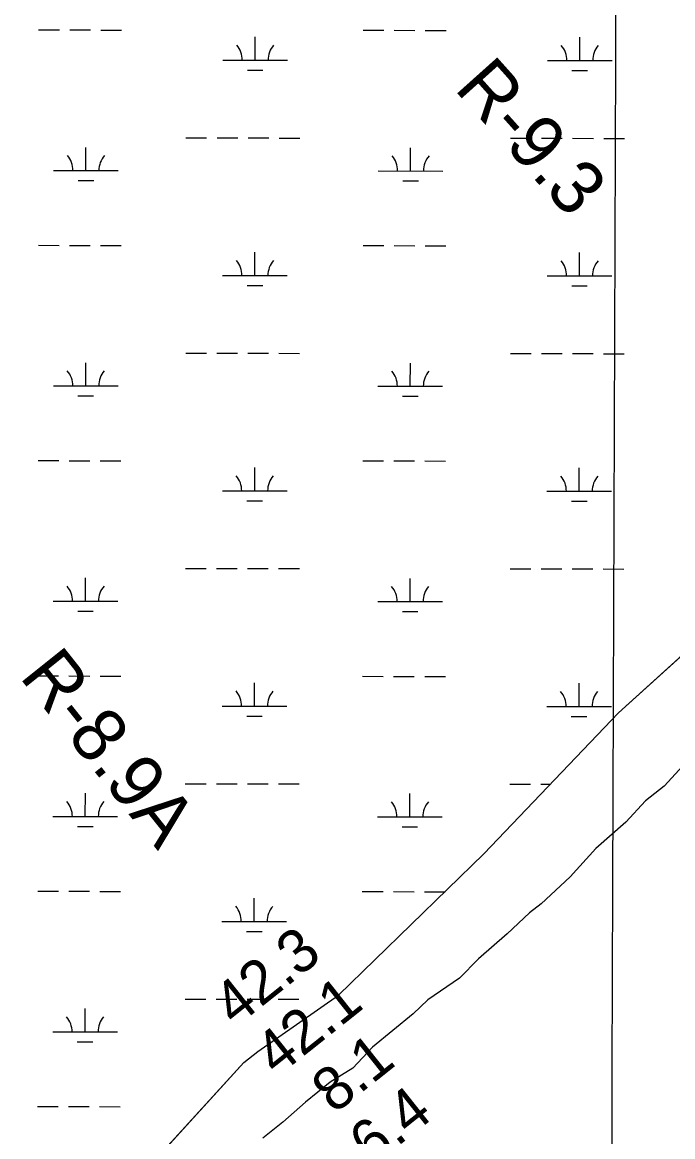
# Model space of a CAD drawing. Extents: x 3148686 to 3186545, y 916144 to 941516.
# Drawn here: x 3154623 to 3155629, y 922106 to 923828 of the extents above; entities that cross this region are included whole.
import ezdxf

# ---------------------------------------------------------------- set-up
doc = ezdxf.new("R2010")
doc.units = 0
for name, color, linetype in [('V-GRID-MAJR', 7, 'Continuous'), ('V-RIVR-EDGE', 7, 'Continuous'), ('V-RIVR-RANG', 7, 'Continuous'), ('V-RIVR-RANG-IDEN', 7, 'Continuous'), ('V-SITE-VEGE', 7, 'Continuous'), ('V-WETL-SWMP', 7, 'Continuous')]:
    doc.layers.add(name, color=color, linetype=linetype)

msp = doc.modelspace()

# ---------------------------------------------------------------- linework, layer by layer
at = {"layer": 'V-GRID-MAJR'}
msp.add_spline([(3155532.8, 921545.6), (3155553.9, 927607.5), (3155575.1, 933670.5), (3155596.3, 939733.5), (3155596.3, 939734.6)], degree=3, dxfattribs=at)
at = {"layer": 'V-RIVR-EDGE'}
msp.add_lwpolyline([(3155667.2, 922703.8), (3155615.3, 922647.6), (3155586.9, 922624.6), (3155556.3, 922591.7), (3155509.8, 922551.4), (3155470.3, 922507.5), (3155425.2, 922465.8), (3155407.1, 922451.6), (3155372.9, 922419.4), (3155328.5, 922380.9), (3155299, 922350.8), (3155250.3, 922317.3), (3155227.6, 922296), (3155164.4, 922244.1), (3155134.1, 922211.9), (3155099, 922190.3), (3155061, 922159.2), (3155026.1, 922128.5), (3154995.2, 922103.7)], dxfattribs=at)
at = {"layer": 'V-SITE-VEGE'}
for p, q in [((3155545.1, 922760.8), (3155916.4, 923097.1)), ((3155336.9, 922542.9), (3155545.1, 922760.8)), ((3155112, 922324.4), (3155336.9, 922542.9)), ((3154987, 922237.4), (3155112, 922324.4)), ((3154965.6, 922220.8), (3154987, 922237.4)), ((3154789.5, 922027.6), (3154965.6, 922220.8))]:
    msp.add_line(p, q, dxfattribs=at)
at = {"layer": 'V-WETL-SWMP'}
for p, q in [((3154648.3, 923815.8), (3154680.3, 923815.8)), ((3154696.3, 923815.8), (3154728.3, 923815.8)), ((3154744.3, 923815.7), (3154776.3, 923815.7)), ((3154983.1, 923769.1), (3154983.1, 923805.1)), ((3155150.2, 923815.3), (3155182.2, 923815.3)), ((3155198.2, 923815.3), (3155230.2, 923815.2)), ((3155246.2, 923815.2), (3155278.2, 923815.2)), ((3155485, 923768.5), (3155485, 923804.5)), ((3154933.1, 923769.1), (3155033.1, 923769)), ((3155435, 923768.6), (3155535, 923768.5)), ((3154971.1, 923753.6), (3154995.1, 923753.6)), ((3155473, 923753.1), (3155497, 923753.1)), ((3154876.1, 923649.1), (3154908.1, 923649.1)), ((3154924.1, 923649), (3154956.1, 923649)), ((3154972.1, 923649), (3155004.1, 923649)), ((3155020.1, 923648.9), (3155052.1, 923648.9)), ((3155378, 923648.6), (3155410, 923648.5)), ((3155426, 923648.5), (3155458, 923648.5)), ((3155474, 923648.5), (3155506, 923648.4)), ((3155522, 923648.4), (3155554, 923648.4)), ((3154721.5, 923598.5), (3154721.5, 923634.5)), ((3155223.4, 923598), (3155223.4, 923634)), ((3154671.5, 923598.6), (3154771.5, 923598.5)), ((3155173.4, 923598), (3155273.4, 923597.9)), ((3154709.5, 923583.1), (3154733.5, 923583.1)), ((3155211.4, 923582.6), (3155235.4, 923582.5)), ((3154647.9, 923483.2), (3154679.9, 923483.1)), ((3154695.9, 923483.1), (3154727.9, 923483.1)), ((3154743.9, 923483.1), (3154775.9, 923483)), ((3155149.9, 923482.6), (3155181.9, 923482.6)), ((3155197.9, 923482.6), (3155229.9, 923482.5)), ((3155245.9, 923482.5), (3155277.9, 923482.5)), ((3154982.7, 923436.4), (3154982.8, 923472.4)), ((3155484.7, 923435.8), (3155484.7, 923471.8)), ((3154932.7, 923436.4), (3155032.7, 923436.3)), ((3155434.7, 923435.9), (3155534.7, 923435.8)), ((3154970.7, 923421), (3154994.7, 923420.9)), ((3155472.6, 923420.4), (3155496.6, 923420.4)), ((3154721.1, 923265.8), (3154721.2, 923301.8)), ((3154875.8, 923316.4), (3154907.8, 923316.4)), ((3154923.8, 923316.4), (3154955.8, 923316.3)), ((3154971.8, 923316.3), (3155003.8, 923316.3)), ((3155019.8, 923316.3), (3155051.8, 923316.2)), ((3155223, 923265.3), (3155223.1, 923301.3)), ((3155377.7, 923315.9), (3155409.7, 923315.9)), ((3155425.7, 923315.8), (3155457.7, 923315.8)), ((3155473.7, 923315.8), (3155505.7, 923315.8)), ((3155521.7, 923315.7), (3155553.7, 923315.7)), ((3154671.1, 923265.9), (3154771.1, 923265.8)), ((3154709.1, 923250.4), (3154733.1, 923250.4)), ((3155173, 923265.4), (3155273, 923265.3)), ((3155211, 923249.9), (3155235, 923249.9)), ((3154647.6, 923150.5), (3154679.6, 923150.5)), ((3154695.6, 923150.4), (3154727.6, 923150.4)), ((3154743.6, 923150.4), (3154775.6, 923150.4)), ((3155149.5, 923150), (3155181.5, 923149.9)), ((3155197.5, 923149.9), (3155229.5, 923149.9)), ((3155245.5, 923149.9), (3155277.5, 923149.8)), ((3154982.4, 923103.7), (3154982.4, 923139.7)), ((3155484.3, 923103.2), (3155484.3, 923139.2)), ((3154932.4, 923103.8), (3155032.4, 923103.7)), ((3155434.3, 923103.2), (3155534.3, 923103.1)), ((3154970.4, 923088.3), (3154994.4, 923088.3)), ((3155472.3, 923087.8), (3155496.3, 923087.7)), ((3154875.4, 922983.7), (3154907.4, 922983.7)), ((3154923.4, 922983.7), (3154955.4, 922983.7)), ((3154971.4, 922983.6), (3155003.4, 922983.6)), ((3155019.4, 922983.6), (3155051.4, 922983.6)), ((3155377.3, 922983.2), (3155409.3, 922983.2)), ((3155425.3, 922983.2), (3155457.3, 922983.1)), ((3155473.3, 922983.1), (3155505.3, 922983.1)), ((3155521.3, 922983.1), (3155553.3, 922983)), ((3154720.8, 922933.2), (3154720.8, 922969.2)), ((3155222.7, 922932.6), (3155222.7, 922968.6)), ((3154670.8, 922933.2), (3154770.8, 922933.1)), ((3155172.7, 922932.7), (3155272.7, 922932.6)), ((3154708.8, 922917.7), (3154732.8, 922917.7)), ((3155210.7, 922917.2), (3155234.7, 922917.2)), ((3154647.2, 922817.8), (3154679.2, 922817.8)), ((3154695.2, 922817.8), (3154727.2, 922817.7)), ((3154743.2, 922817.7), (3154775.2, 922817.7)), ((3154982, 922771), (3154982.1, 922807)), ((3155149.2, 922817.3), (3155181.2, 922817.2)), ((3155197.2, 922817.2), (3155229.2, 922817.2)), ((3155245.2, 922817.2), (3155277.2, 922817.1)), ((3155483.9, 922770.5), (3155484, 922806.5)), ((3154932, 922771.1), (3155032, 922771)), ((3155433.9, 922770.6), (3155533.9, 922770.4)), ((3154970, 922755.6), (3154994, 922755.6)), ((3155471.9, 922755.1), (3155495.9, 922755.1)), ((3154875.1, 922651.1), (3154907.1, 922651)), ((3154923.1, 922651), (3154955.1, 922651)), ((3154971.1, 922651), (3155003.1, 922650.9)), ((3155019.1, 922650.9), (3155051.1, 922650.9)), ((3155377, 922650.5), (3155409, 922650.5)), ((3155425, 922650.5), (3155439.7, 922650.5)), ((3154720.4, 922600.5), (3154720.5, 922636.5)), ((3155222.3, 922600), (3155222.4, 922636)), ((3154670.4, 922600.5), (3154770.4, 922600.4)), ((3155172.3, 922600), (3155272.3, 922599.9)), ((3154708.4, 922585.1), (3154732.4, 922585)), ((3155210.3, 922584.5), (3155234.3, 922584.5)), ((3154646.9, 922485.1), (3154678.9, 922485.1)), ((3154694.9, 922485.1), (3154726.9, 922485.1)), ((3154742.9, 922485), (3154774.9, 922485)), ((3154981.7, 922438.4), (3154981.7, 922474.4)), ((3155148.8, 922484.6), (3155180.8, 922484.6)), ((3155196.8, 922484.6), (3155228.8, 922484.5)), ((3155244.8, 922484.5), (3155276.8, 922484.5)), ((3154931.7, 922438.4), (3155031.7, 922438.3)), ((3154969.7, 922422.9), (3154993.7, 922422.9)), ((3154720.1, 922267.8), (3154720.1, 922303.8)), ((3154874.7, 922318.4), (3154906.7, 922318.4)), ((3154922.7, 922318.3), (3154954.7, 922318.3)), ((3154970.7, 922318.3), (3155002.7, 922318.3)), ((3155018.7, 922318.2), (3155050.7, 922318.2)), ((3154670.1, 922267.9), (3154770.1, 922267.8)), ((3154708.1, 922252.4), (3154732.1, 922252.4)), ((3154646.5, 922152.5), (3154678.5, 922152.4)), ((3154694.5, 922152.4), (3154726.5, 922152.4)), ((3154742.5, 922152.4), (3154774.5, 922152.3))]:
    msp.add_line(p, q, dxfattribs=at)
msp.add_lwpolyline([(3154789.5, 922027.6), (3154965.6, 922220.8), (3154987, 922237.4), (3155112, 922324.4), (3155336.9, 922542.9), (3155545.1, 922760.8), (3155916.4, 923097.1)], dxfattribs=at)
for centre, start, end in [((3154927.9, 923769.6), 359.1678, 40.7115), ((3155038.3, 923769.5), 139.1678, 180.7115), ((3155429.8, 923769.1), 359.1678, 40.7115), ((3155540.2, 923768.9), 139.1678, 180.7115), ((3154666.2, 923599), 359.1678, 40.7115), ((3154776.7, 923598.9), 139.1678, 180.7115), ((3155168.1, 923598.5), 359.1678, 40.7115), ((3155278.6, 923598.4), 139.1678, 180.7115), ((3154927.5, 923436.9), 359.1678, 40.7115), ((3155038, 923436.8), 139.1678, 180.7115), ((3155429.4, 923436.4), 359.1678, 40.7115), ((3155539.9, 923436.3), 139.1678, 180.7115), ((3154665.9, 923266.4), 359.1678, 40.7115), ((3154776.4, 923266.3), 139.1678, 180.7115), ((3155167.8, 923265.8), 359.1678, 40.7115), ((3155278.3, 923265.7), 139.1678, 180.7115), ((3154927.1, 923104.2), 359.1678, 40.7115), ((3155037.6, 923104.1), 139.1678, 180.7115), ((3155429.1, 923103.7), 359.1678, 40.7115), ((3155539.5, 923103.6), 139.1678, 180.7115), ((3154665.5, 922933.7), 359.1678, 40.7115), ((3154776, 922933.6), 139.1678, 180.7115), ((3155167.4, 922933.2), 359.1678, 40.7115), ((3155277.9, 922933.1), 139.1678, 180.7115), ((3154926.8, 922771.6), 359.1678, 40.7115), ((3155037.3, 922771.4), 139.1678, 180.7115), ((3155428.7, 922771), 359.1678, 40.7115), ((3155539.2, 922770.9), 139.1678, 180.7115), ((3154665.2, 922601), 359.1678, 40.7115), ((3154775.7, 922600.9), 139.1678, 180.7115), ((3155167.1, 922600.5), 359.1678, 40.7115), ((3155277.6, 922600.4), 139.1678, 180.7115), ((3154926.4, 922438.9), 359.1678, 40.7115), ((3155036.9, 922438.8), 139.1678, 180.7115), ((3154664.8, 922268.3), 359.1678, 40.7115), ((3154775.3, 922268.2), 139.1678, 180.7115)]:
    msp.add_arc(centre, 35.2, start, end, dxfattribs=at)

# ---------------------------------------------------------------- texts
at = {"layer": 'V-RIVR-RANG'}
for s, p in [('42.3', (3154952.6, 922274.1)), ('42.1', (3155016.9, 922197.4)), ('8.1', (3155105.3, 922140)), ('-6.4', (3155139.9, 922039.8))]:
    msp.add_text(s, height=67, rotation=38.5083, dxfattribs=at).set_placement(p)
at = {"layer": 'V-RIVR-RANG-IDEN'}
for s, rotation, p in [('R-9.3', 311.8446, (3155289.5, 923724.8)), ('R-8.9A', 308.6517, (3154617.3, 922816.6))]:
    msp.add_text(s, height=83, rotation=rotation, dxfattribs=at).set_placement(p)

doc.saveas('drawing.dxf')
